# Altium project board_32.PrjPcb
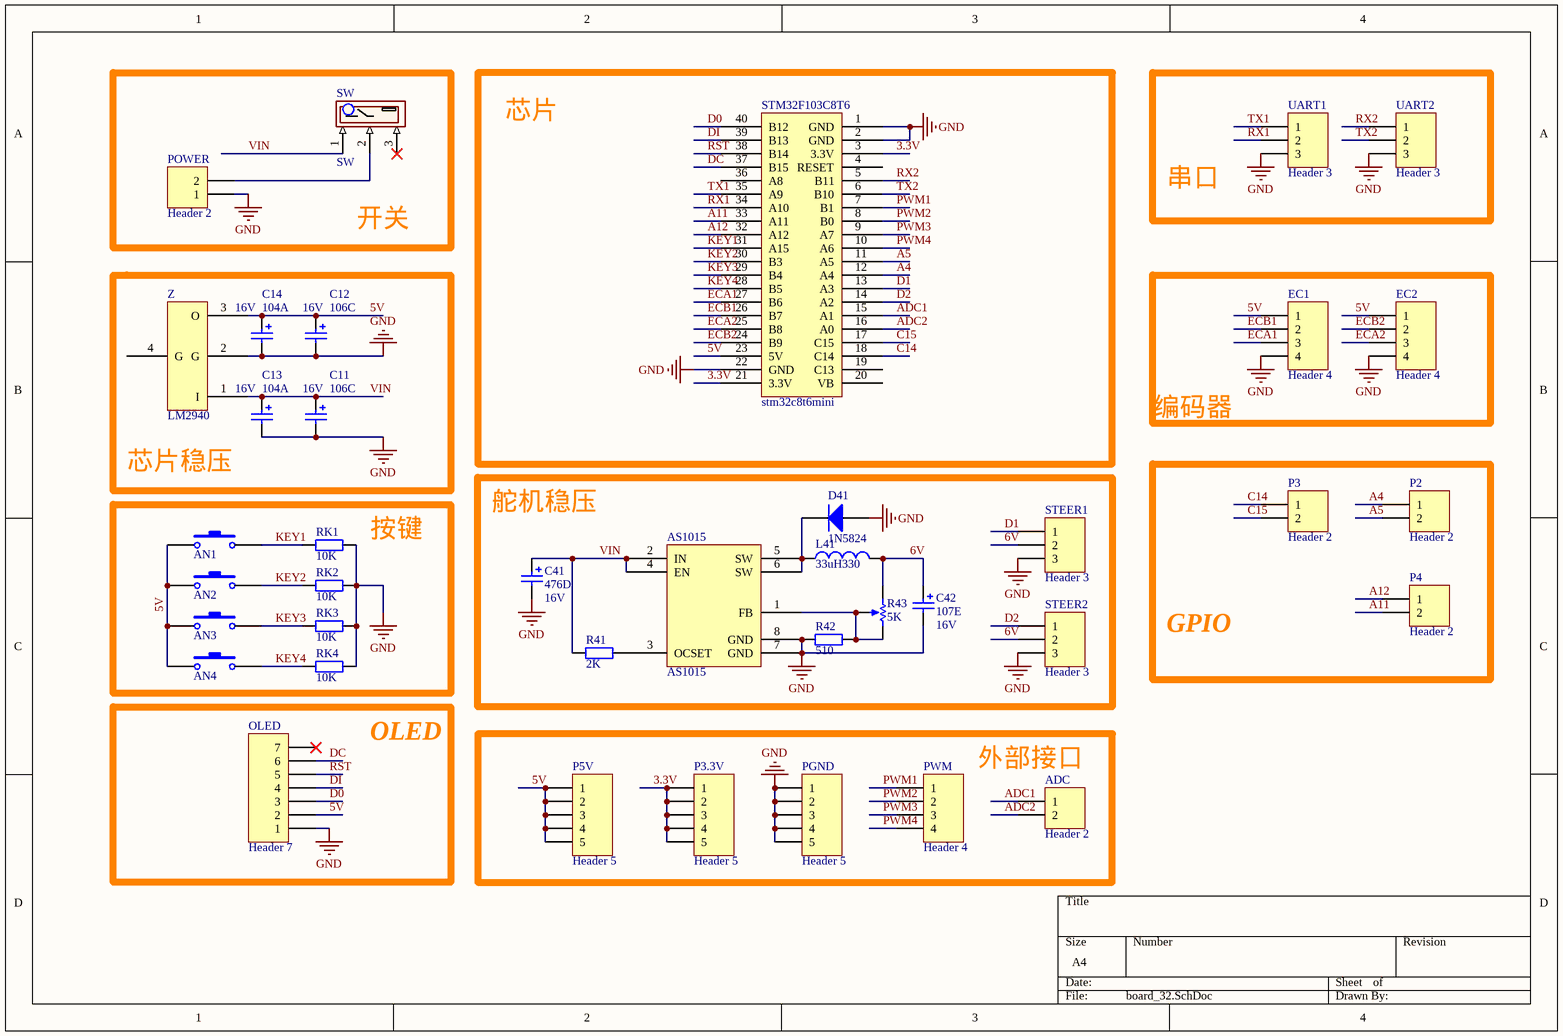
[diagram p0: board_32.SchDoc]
1 sheet, 39 parts. Net scope: global (net labels, ports and power ports of the same name join across sheets).
Board file: board_32.PcbDoc

## Sheet board_32.SchDoc
size A4

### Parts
ADC  Header 2  [HDR1X2]
AN1  Button  [SMT4*6.2*4]  (value not drawn)
AN2  Button  [SMT4*6.2*4]  (value not drawn)
AN3  Button  [SMT4*6.2*4]  (value not drawn)
AN4  Button  [SMT4*6.2*4]  (value not drawn)
AS1015  AS1015  [SOP-8N]
C11  Capacitance: 106C  Voltage: 16V  [TAN-C-6032]  (hidden comment: Cap Tan C)
C12  Capacitance: 106C  Voltage: 16V  [TAN-C-6032]  (hidden comment: Cap Tan C)
C13  value 104A  Voltage: 16V  [TAN-A-3216]  (hidden comment: Cap Tan A)
C14  value 104A  Voltage: 16V  [TAN-A-3216]  (hidden comment: Cap Tan A)
C41  Capacitance: 476D  Voltage: 16V  [C7361]  (hidden comment: Cap Tan E)
C42  Capacitance: 107E  Voltage: 16V  [TAN-E-7361]  (hidden comment: Cap Tan E)
D41  1N5824  [SMB]
EC1  Header 4  [HDR1X4]
EC2  Header 4  [HDR1X4]
L41  value 33uH330  [CD75NP]  (hidden comment: Inductor)
OLED  Header 7  [HDR1X7]
P2  Header 2  [HDR1X2]
P3  Header 2  [HDR1X2]
P3.3V  Header 5  [HDR1X5]
P4  Header 2  [HDR1X2]
P5V  Header 5  [HDR1X5]
PGND  Header 5  [HDR1X5]
POWER  Header 2  [2PIN-5.08A]
PWM  Header 4  [HDR1X4]
R41  value 2K  [R0805]  (hidden comment: Resistor Chip 0805)
R42  value 510  [R0805]  (hidden comment: Resistor Chip 0805)
R43  value 5K  [VR_B1]  (hidden comment: RPot)
RK1  value 10K  [R0805]  (hidden comment: Resistor Chip 0805)
RK2  value 10K  [R0805]  (hidden comment: Resistor Chip 0805)
RK3  value 10K  [R0805]  (hidden comment: Resistor Chip 0805)
RK4  value 10K  [R0805]  (hidden comment: Resistor Chip 0805)
STEER1  Header 3  [HDR1X3]
STEER2  Header 3  [HDR1X3]
STM32F103C8T6  stm32c8t6mini  [DIP-40]
SW  SW  [SW-TO3]
UART1  Header 3  [HDR1X3]
UART2  Header 3  [HDR1X3]
Z  LM2940  [TO-220E]

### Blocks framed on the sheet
开关: POWER SW
芯片: STM32F103C8T6
串口: UART1 UART2
芯片稳压: C11-C14 Z
编码器: EC1 EC2
按键: AN1-AN4 RK1-RK4
舵机稳压: AS1015 C41 C42 D41 L41 R41-R43 STEER1 STEER2
GPIO: P2-P4
OLED: OLED
外部接口: ADC P3.3V P5V PGND PWM

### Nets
GND: AS1015.7(GND) AS1015.8(GND) C11.1 C12.1 C13.1 C14.1 C41.1 C42.1 D41.1(A) EC1.4 EC2.4 OLED.1 PGND.1 PGND.2 PGND.3 PGND.4 PGND.5 POWER.1 R42.1 RK1.2 RK2.2 RK3.2 RK4.2 STEER1.3 STEER2.3 STM32F103C8T6.1(GND) STM32F103C8T6.2(GND) STM32F103C8T6.22(GND) UART1.3 UART2.3 Z.2(G)
3.3V: P3.3V.1 P3.3V.2 P3.3V.3 P3.3V.4 P3.3V.5 STM32F103C8T6.3(3.3V) STM32F103C8T6.21(3.3V)
5V: AN1.2 AN2.2 AN3.2 AN4.2 C12.2 C14.2 EC1.1 EC2.1 OLED.2 P5V.1 P5V.2 P5V.3 P5V.4 P5V.5 STM32F103C8T6.23(5V) Z.3(O)
6V: C42.2 L41.2 R43.1(TOP) STEER1.2 STEER2.2
A4: P2.1 STM32F103C8T6.12(A4)
A5: P2.2 STM32F103C8T6.11(A5)
A11: P4.2 STM32F103C8T6.33(A11)
A12: P4.1 STM32F103C8T6.32(A12)
ADC1: ADC.1 STM32F103C8T6.15(A1)
ADC2: ADC.2 STM32F103C8T6.16(A0)
C14: P3.1 STM32F103C8T6.18(C14)
C15: P3.2 STM32F103C8T6.17(C15)
D0: OLED.3 STM32F103C8T6.40(B12)
D1: STEER1.1 STM32F103C8T6.13(A3)
D2: STEER2.1 STM32F103C8T6.14(A2)
DC: OLED.6 STM32F103C8T6.37(B15)
DI: OLED.4 STM32F103C8T6.39(B13)
ECA1: EC1.3 STM32F103C8T6.27(B6)
ECA2: EC2.3 STM32F103C8T6.25(B8)
ECB1: EC1.2 STM32F103C8T6.26(B7)
ECB2: EC2.2 STM32F103C8T6.24(B9)
KEY1: AN1.1 RK1.1 STM32F103C8T6.31(A15)
KEY2: AN2.1 RK2.1 STM32F103C8T6.30(B3)
KEY3: AN3.1 RK3.1 STM32F103C8T6.29(B4)
KEY4: AN4.1 RK4.1 STM32F103C8T6.28(B5)
PWM1: PWM.1 STM32F103C8T6.7(B1)
PWM2: PWM.2 STM32F103C8T6.8(B0)
PWM3: PWM.3 STM32F103C8T6.9(A7)
PWM4: PWM.4 STM32F103C8T6.10(A6)
RST: OLED.5 STM32F103C8T6.38(B14)
RX1: STM32F103C8T6.34(A10) UART1.2
RX2: STM32F103C8T6.5(B11) UART2.1
TX1: STM32F103C8T6.35(A9) UART1.1
TX2: STM32F103C8T6.6(B10) UART2.2
VIN: AS1015.2(IN) AS1015.4(EN) C11.2 C13.2 C41.2 R41.1 SW.1 Z.1(I)
NetAS1015_1: AS1015.1(FB) R42.2 R43.2(TAP) R43.3(BOT)
NetAS1015_3: AS1015.3(OCSET) R41.2
NetAS1015_5: AS1015.5(SW) AS1015.6(SW) D41.2(K) L41.1
NetPOWER_2: POWER.2 SW.2

Not connected (* = marked no-connect by the designer): OLED 7*; STM32F103C8T6 4(RESET) 19(C13) 20(VB) 36(A8); SW 3*; Z 4(G)

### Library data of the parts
ADC P2-P4 POWER = Header 2: Header, 2-Pin
C11 C12 = Cap Tan C: Polarized Capacitor (Radial)
C13 C14 = Cap Tan A: Polarized Capacitor (Radial)
C41 C42 = Cap Tan E: Polarized Capacitor (Radial)
D41 = 1N4007: 1.0 Ampere General Purpose Rectifier
EC1 EC2 PWM = Header 4: Header, 4-Pin
L41 = Inductor: Code_IEC: 1005
OLED = Header 7: Header, 7-Pin
P3.3V P5V PGND = Header 5: Header, 5-Pin
R41 R42 RK1-RK4 = Resistor Chip 0805: Resistor
R43 = RPot: 精密可调电阻; Sim Note: Enter the Resistance value and the set point into parameter fields.; Set Position: 0.5
STEER1 STEER2 UART1 UART2 = Header 3: Header, 3-Pin
SW = 开关三脚大电流
Z = LM2940: SOT-223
